// Mitsubishi GX Works2 project: jk3u主站   PLC: FX3U/FX3UC

PROGRAM MAIN
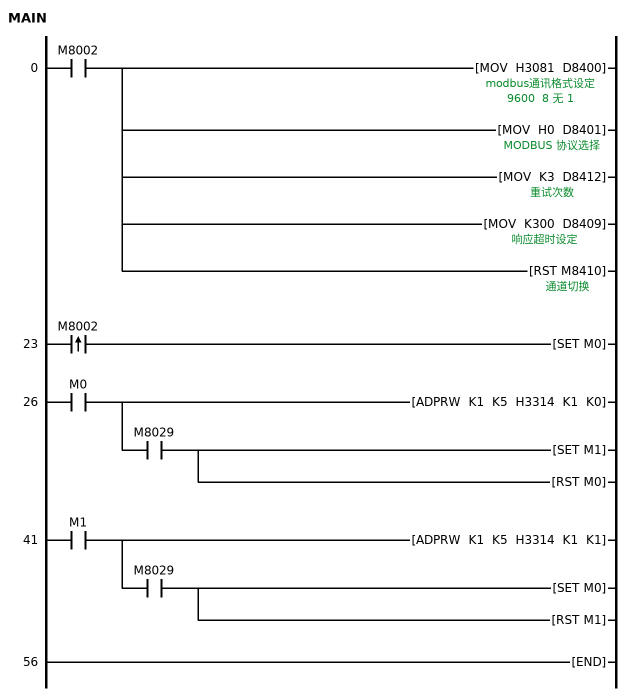
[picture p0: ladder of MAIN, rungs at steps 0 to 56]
0     LD      M8002
      MOV     H3081 D8400  ; modbus通讯格式设定  9600  8 无 1
      MOV     H0 D8401  ; MODBUS 协议选择
      MOV     K3 D8412  ; 重试次数
      MOV     K300 D8409  ; 响应超时设定
      RST     M8410  ; 通道切换
23    LDP     M8002
      SET     M0
26    LD      M0
      ADPRW   K1 K5 H3314 K1 K0
      AND     M8029
      SET     M1
      RST     M0
41    LD      M1
      ADPRW   K1 K5 H3314 K1 K1
      AND     M8029
      SET     M0
      RST     M1
56    END
END_PROGRAM
